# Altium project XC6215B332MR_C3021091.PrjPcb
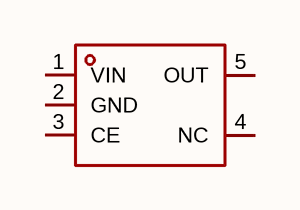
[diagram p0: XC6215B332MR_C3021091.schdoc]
1 sheet, 1 parts. Net scope: global (net labels, ports and power ports of the same name join across sheets).

## Sheet XC6215B332MR_C3021091.schdoc
size 127 x 101 mm

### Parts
U?  xc6215b332mr  [SOT-23-5_L2.9-W1.6-P0.95-LS2.8-BR]  (value not drawn)

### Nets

Not connected (* = marked no-connect by the designer): U? 1(VIN) 2(GND) 3(CE) 4(NC) 5(OUT)

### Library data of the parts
U? = xc6215b332mr: 输出极性:正极;工作电压:5.5V;输出电压:3.3V;输出电流:300mA;电源纹波抑制比(PSRR):80dB@(1kHz);输出类型:固定;; Manufacturer: TECH PUBLIC(台舟); Symbol: XC6215B332MR_C3021091; AddInBom: yes; ModelId: 7ba65df16e7b4570af156e925f9c37fe; ModelTransform: 114.173,114.173,0,90,0,0,0,0,0; Output Configuration: 正极; Voltage - Supply: 5.5V; Output Voltage: 3.3V; Output Current: 300mA; Voltage Dropout: 180mV@(300mA); standby current: 2uA; Noise: 80uVrms; Output Type: 固定; Number of Outputs: 1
